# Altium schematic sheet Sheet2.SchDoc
size A4; SheetNumber: 1; SheetTotal: 2
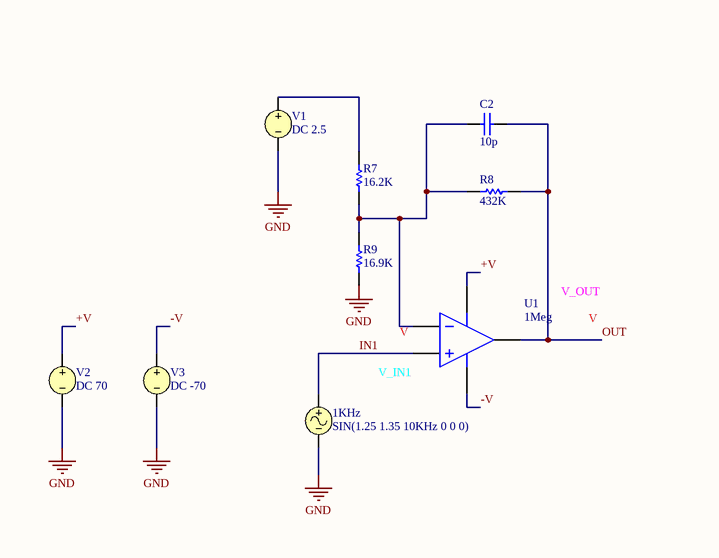
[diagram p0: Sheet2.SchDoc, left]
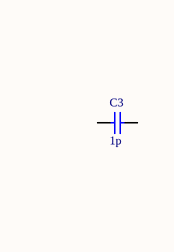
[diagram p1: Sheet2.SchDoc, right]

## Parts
1KHz  SIN(1.25 1.35 10KHz 0 0 0)
C2  value 10p  (hidden comment: Capacitor)
C3  value 1p  (hidden comment: Capacitor)
R7  value 16.2K  (hidden comment: Resistor)
R8  value 432K  (hidden comment: Resistor)
R9  value 16.9K  (hidden comment: Resistor)
U1  GAIN: 1Meg  (hidden comment: Ideal Operational Amplifier)
V1  DC 2.5
V2  DC 70
V3  DC -70

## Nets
GND: 1KHz.2 R9.1 V1.2 V2.2 V3.2
+V: U1.4(V+) V2.1
-V: U1.5(V-) V3.1
IN1: 1KHz.1 U1.2(IN+)
OUT: C2.2 R8.1 U1.3(OUT)
NetC2_1: C2.1 R7.1 R8.2 R9.2 U1.1(IN-)
NetR7_2: R7.2 V1.1

Not connected (* = marked no-connect by the designer): C3 1 2

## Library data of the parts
1KHz = VSIN: Sinusoidal Voltage Source; Note: PCB Footprint - Not required; Offset: 1.25; Amplitude: 1.35; Delay: 0; AC Magnitude: 1
C2 C3 = Capacitor: SimulationGenericComponent: True
R7-R9 = Resistor: TC1: 0; SimulationGenericComponent: True
U1 = OpAmp with power terminals: SimulationGenericComponent: True
V1 = VSRC: Voltage Source; Note: PCB Footprint - Not required; AC Magnitude: 1; AC Phase: 0; Value: 2.5
V2 = VSRC: Voltage Source; Note: PCB Footprint - Not required; AC Magnitude: 1; AC Phase: 0; Value: 70
V3 = VSRC: Voltage Source; Note: PCB Footprint - Not required; AC Magnitude: 1; AC Phase: 0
